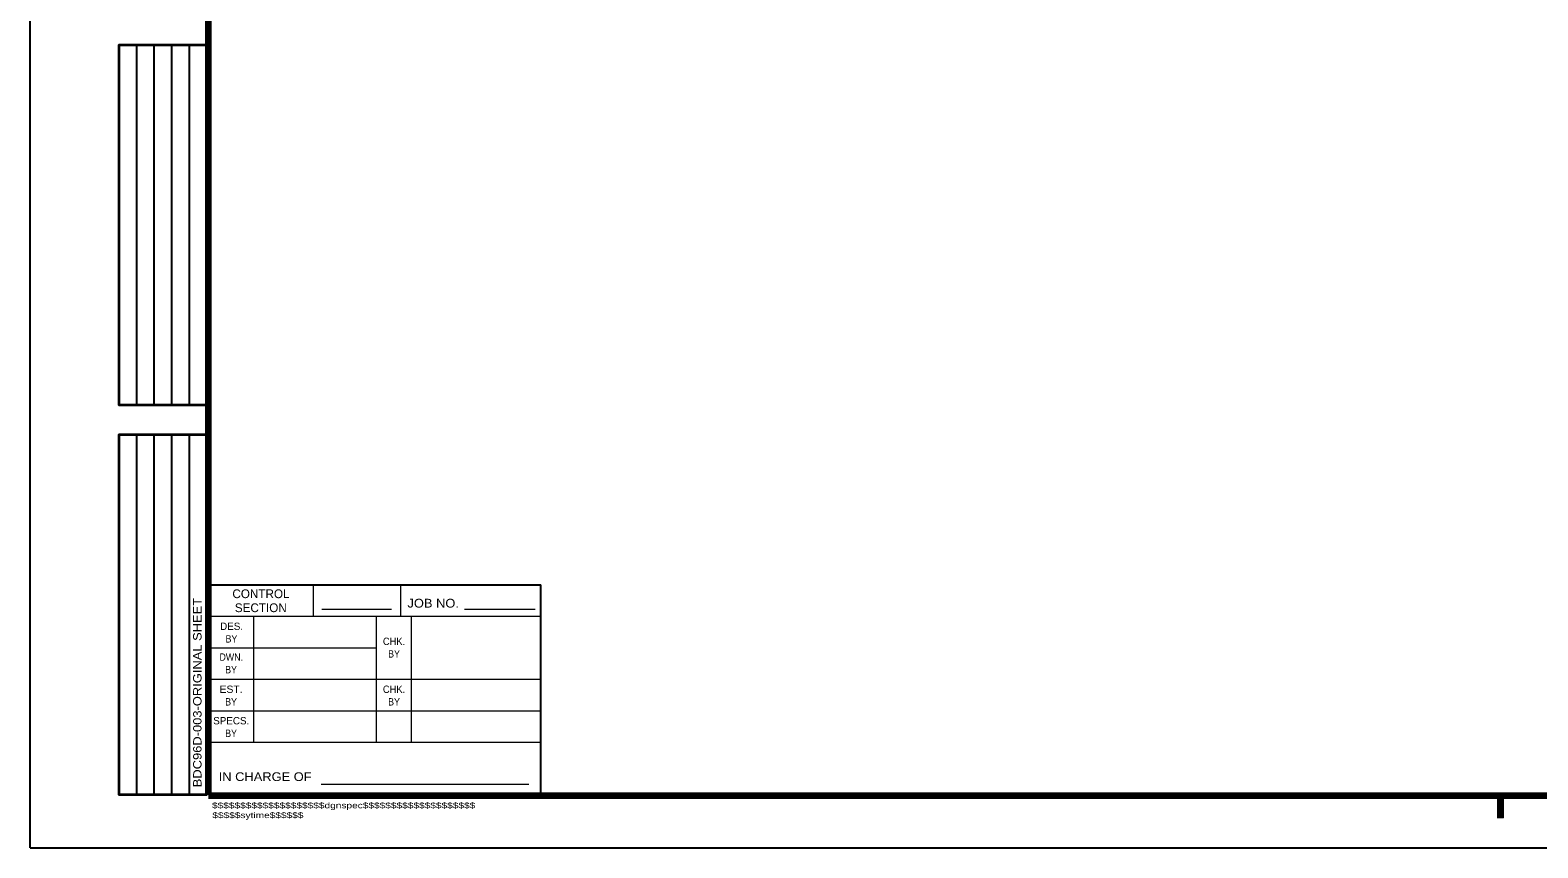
# Model space of a CAD drawing. Extents: x 312601.858 to 312602.699, y 144420.109 to 144420.704.
# Drawn here: x 312601.8578 to 312602.2889, y 144420.1095 to 144420.3433 of the extents above; entities that cross this region are included whole.
import ezdxf
from ezdxf.enums import TextEntityAlignment as Align

# ---------------------------------------------------------------- set-up
doc = ezdxf.new("R2010")
doc.units = 0
doc.header["$LTSCALE"] = 0.0012
for name, color, linetype, lineweight in [('1', 7, 'Continuous', 25), ('2', 7, 'Continuous', 13), ('39', 7, 'Continuous', 13), ('60', 7, 'Continuous', 25)]:
    doc.layers.add(name, color=color, linetype=linetype, lineweight=lineweight)

msp = doc.modelspace()

# ---------------------------------------------------------------- linework, layer by layer
at = {"layer": '1', "lineweight": 158}
msp.add_line((312602.2782, 144420.118), (312602.2782, 144420.1244), dxfattribs=at)
at = {"layer": '39', "lineweight": 25}
for p, q in [((312601.8578, 144420.1095), (312601.8578, 144420.7035)), ((312601.9088, 144420.1847), (312602.0038, 144420.1847)), ((312602.0038, 144420.1247), (312602.0038, 144420.1847)), ((312601.8578, 144420.1095), (312602.6988, 144420.1095))]:
    msp.add_line(p, q, dxfattribs=at)
at = {"layer": '39', "lineweight": 158}
for p, q in [((312601.9088, 144420.1247), (312601.9088, 144420.6645)), ((312601.9088, 144420.1245), (312602.6838, 144420.1245)), ((312602.2783, 144420.1181), (312602.2783, 144420.1245))]:
    msp.add_line(p, q, dxfattribs=at)
at = {"layer": '39'}
for p, q in [((312601.9088, 144420.1247), (312601.9088, 144420.1847)), ((312601.9388, 144420.1757), (312601.9388, 144420.1847)), ((312601.9638, 144420.1757), (312601.9638, 144420.1847)), ((312601.9088, 144420.1757), (312602.0038, 144420.1757)), ((312601.9218, 144420.1397), (312601.9218, 144420.1757)), ((312601.9412, 144420.1777), (312601.9611, 144420.1777)), ((312601.9568, 144420.1397), (312601.9568, 144420.1757)), ((312601.9668, 144420.1397), (312601.9668, 144420.1757)), ((312601.982, 144420.1777), (312602.0022, 144420.1777)), ((312601.9088, 144420.1667), (312601.9568, 144420.1667)), ((312601.9088, 144420.1577), (312602.0038, 144420.1577)), ((312601.9088, 144420.1487), (312602.0038, 144420.1487)), ((312601.9088, 144420.1397), (312602.0038, 144420.1397)), ((312601.941, 144420.1277), (312602.0004, 144420.1277)), ((312601.9088, 144420.1247), (312602.0038, 144420.1247))]:
    msp.add_line(p, q, dxfattribs=at)
at = {"layer": '60'}
for p, q in [((312601.8883, 144420.2361), (312601.8883, 144420.3391)), ((312601.8933, 144420.2361), (312601.8933, 144420.3391)), ((312601.8983, 144420.2361), (312601.8983, 144420.3391)), ((312601.9034, 144420.2361), (312601.9034, 144420.3391)), ((312601.8883, 144420.1247), (312601.8883, 144420.2277)), ((312601.8933, 144420.1247), (312601.8933, 144420.2277)), ((312601.8983, 144420.1247), (312601.8983, 144420.2277)), ((312601.9034, 144420.1247), (312601.9034, 144420.2277))]:
    msp.add_line(p, q, dxfattribs=at)
at = {"layer": '60', "lineweight": 35}
for points in [[(312601.9084, 144420.2361), (312601.8833, 144420.2361), (312601.8833, 144420.3391), (312601.9084, 144420.3391)], [(312601.9084, 144420.1247), (312601.8833, 144420.1247), (312601.8833, 144420.2277), (312601.9084, 144420.2277)]]:
    msp.add_lwpolyline(points, dxfattribs=at)

# ---------------------------------------------------------------- texts
at = {"layer": '1'}
for s, height, p in [('CONTROL', 0.0025, (312601.9238, 144420.1809)), ('SECTION', 0.0025, (312601.92375, 144420.1769)), ('DES.', 0.0021, (312601.9154, 144420.1718)), ('SPECS.', 0.0021, (312601.9153, 144420.1448))]:
    msp.add_text(s, height=height, dxfattribs=at).set_placement(p, align=Align.CENTER)
for s, height, width, p in [('JOB NO.', 0.0025, 1.1, (312601.97305, 144420.1782)), ('BY', 0.0021, 0.9, (312601.91535, 144420.1682)), ('CHK.', 0.0021, 0.95, (312601.96185, 144420.1675)), ('BY', 0.0021, 0.9, (312601.96185, 144420.1639)), ('DWN.', 0.0021, 0.9, (312601.9153, 144420.163)), ('BY', 0.0021, 0.9, (312601.91525, 144420.1594)), ('EST.', 0.0021, 1.05, (312601.91525, 144420.1538)), ('CHK.', 0.0021, 0.95, (312601.96185, 144420.1538)), ('BY', 0.0021, 0.9, (312601.91525, 144420.1502)), ('BY', 0.0021, 0.9, (312601.96185, 144420.1502)), ('BY', 0.0021, 0.9, (312601.91525, 144420.1412)), ('IN CHARGE OF', 0.0025, 1.1, (312601.925, 144420.1286))]:
    msp.add_text(s, height=height, dxfattribs=dict(at, width=width)).set_placement(p, align=Align.CENTER)
at = {"layer": '2', "width": 1.15}
msp.add_text('BDC96D-003-ORIGINAL SHEET', height=0.0024, rotation=90, dxfattribs=at).set_placement((312601.9068, 144420.1539), align=Align.CENTER)
at = {"layer": '2', "width": 1.3}
for s, p in [('$$$$$$$$$$$$$$$$$$$$dgnspec$$$$$$$$$$$$$$$$$$$$', (312601.9098, 144420.1208)), ('$$$$$sytime$$$$$$', (312601.9099, 144420.118))]:
    msp.add_text(s, height=0.001664, dxfattribs=at).set_placement(p)

doc.saveas('drawing.dxf')
